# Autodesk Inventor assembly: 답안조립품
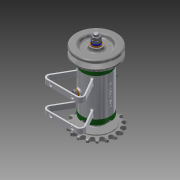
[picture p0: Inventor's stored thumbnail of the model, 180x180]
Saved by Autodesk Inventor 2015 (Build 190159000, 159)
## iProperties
Created: 2016-04
Part Number: 답안조립품
Document SubType Name: Assembly
Designer: Administrator
Author: Administrator
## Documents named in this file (16)
- C:\Users\Administrator\Desktop\460307V1017\460307V1017\답안조립품.iam
- C:\Users\Administrator\Desktop\460307V1017\460307V1017\V벨트풀리.ipt
- C:\Users\Administrator\Desktop\460307V1017\460307V1017\너트 M 8.ipt
- C:\Users\Administrator\Desktop\460307V1017\460307V1017\니플 M 6 x 0.75.ipt
- C:\Users\Administrator\Desktop\460307V1017\460307V1017\베어링 15 x 32 x 9.ipt
- C:\Users\Administrator\Desktop\460307V1017\460307V1017\본체.ipt
- C:\Users\Administrator\Desktop\460307V1017\460307V1017\볼트 M 6 x 8.ipt
- C:\Users\Administrator\Desktop\460307V1017\460307V1017\볼트 M4 x 12.ipt
- C:\Users\Administrator\Desktop\460307V1017\460307V1017\스프로킷.ipt
- C:\Users\Administrator\Desktop\460307V1017\460307V1017\스프링와셔 8.ipt
- C:\Users\Administrator\Desktop\460307V1017\460307V1017\오일 실 15 25 7.ipt
- C:\Users\Administrator\Desktop\460307V1017\460307V1017\와셔 6x11.5.ipt
- C:\Users\Administrator\Desktop\460307V1017\460307V1017\와셔 8x17.ipt
- C:\Users\Administrator\Desktop\460307V1017\460307V1017\축.ipt
- C:\Users\Administrator\Desktop\460307V1017\460307V1017\커버.ipt
- C:\Users\Administrator\Desktop\460307V1017\460307V1017\키 3 x 3 x 12.ipt
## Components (11 placed, 3 different names)
1. V벨트풀리:1 — 각도:7, 각도:9
2. KS B 2023 6002 - 15 x 32 x 9:1
3. KS B 2023 6002 - 15 x 32 x 9:2
4. ISO 4762 M4 x 12:2 — 각도:4
5. ISO 4762 M4 x 12:3
6. ISO 4762 M4 x 12:4
7. ISO 4762 M4 x 12:5
8. ISO 4762 M4 x 12:1 — 각도:3
9. ISO 4762 M4 x 12:6
10. ISO 4762 M4 x 12:7
11. ISO 4762 M4 x 12:8
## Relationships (4: Angle 4)
- 각도:3 [Angle]: ISO 4762 M4 x 12:1
- 각도:4 [Angle]: ISO 4762 M4 x 12:2
- 각도:7 [Angle]: V벨트풀리:1
- 각도:9 [Angle]: V벨트풀리:1
